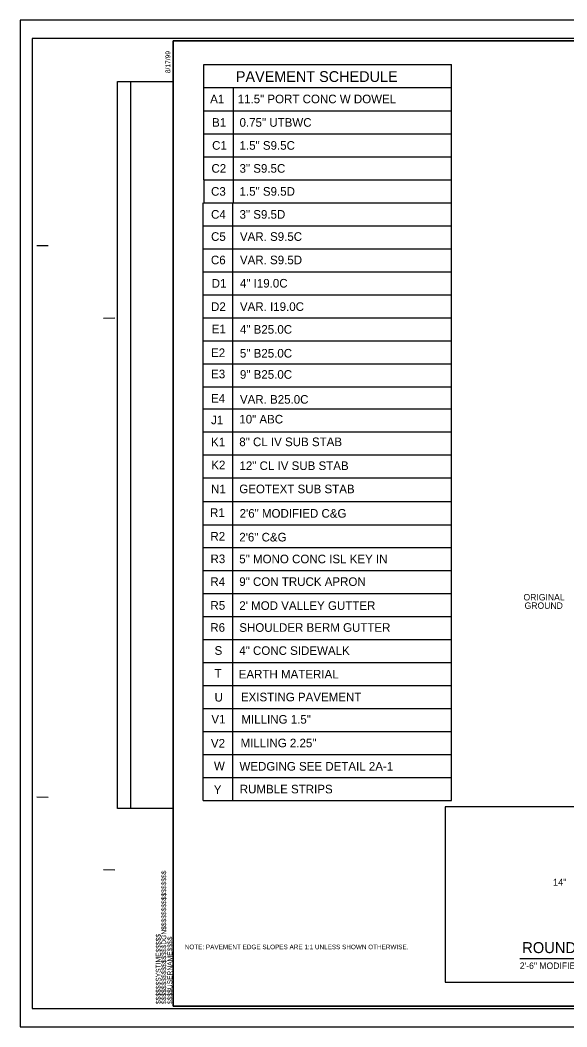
# Model space of a CAD drawing. Extents: x 1640342 to 1730599, y 538663 to 843747.
# Drawn here: x 1729840.7 to 1729959.6, y 538663.2 to 538882.2 of the extents above; entities that cross this region are included whole.
import ezdxf

# ---------------------------------------------------------------- set-up
doc = ezdxf.new("R2010")
doc.units = 0
for name, color, linetype in [('Default', 7, 'Continuous'), ('Old_Level_19', 7, 'Continuous'), ('Old_Level_21', 7, 'Continuous'), ('Sheet Block Revision CELL', 7, 'Continuous'), ('Sheet Plan CELL', 7, 'Continuous'), ('Sheet Plot Border Inside CELL', 7, 'Continuous'), ('Sheet Plot Border Outside CELL', 7, 'Continuous'), ('Typical Text Label CELL', 7, 'Continuous')]:
    doc.layers.add(name, color=color, linetype=linetype)

msp = doc.modelspace()

# ---------------------------------------------------------------- linework, layer by layer
at = {"layer": 'Old_Level_19'}
for p, q in [((1729880.62, 538872.54), (1729934.5, 538872.54)), ((1729880.62, 538867.54), (1729880.62, 538872.54)), ((1729934.5, 538712.47), (1729934.5, 538872.54)), ((1729880.62, 538862.46), (1729880.62, 538867.54)), ((1729880.62, 538867.54), (1729934.5, 538867.54)), ((1729887.11, 538862.46), (1729887.11, 538867.54)), ((1729880.62, 538857.46), (1729880.62, 538862.46)), ((1729880.62, 538862.46), (1729934.5, 538862.46)), ((1729887.11, 538857.46), (1729887.11, 538862.46)), ((1729880.62, 538857.46), (1729934.5, 538857.46)), ((1729880.62, 538852.46), (1729880.62, 538857.46)), ((1729887.11, 538852.46), (1729887.11, 538857.46)), ((1729880.62, 538852.46), (1729934.5, 538852.46)), ((1729880.62, 538847.46), (1729880.62, 538852.46)), ((1729887.11, 538847.46), (1729887.11, 538852.46)), ((1729880.62, 538847.46), (1729880.62, 538842.46)), ((1729880.62, 538847.46), (1729934.5, 538847.46)), ((1729887.11, 538842.46), (1729887.11, 538847.46)), ((1729880.48, 538712.47), (1729880.48, 538842.47)), ((1729880.62, 538842.46), (1729920.63, 538842.46)), ((1729880.62, 538842.46), (1729934.5, 538842.46)), ((1729886.98, 538712.47), (1729886.98, 538842.47)), ((1729880.62, 538837.46), (1729934.5, 538837.46)), ((1729880.62, 538832.46), (1729934.5, 538832.46)), ((1729880.62, 538827.46), (1729934.5, 538827.46)), ((1729880.62, 538822.46), (1729934.5, 538822.46)), ((1729880.62, 538817.46), (1729934.5, 538817.46)), ((1729880.62, 538812.46), (1729934.5, 538812.46)), ((1729880.62, 538807.46), (1729934.5, 538807.46)), ((1729880.62, 538802.46), (1729934.5, 538802.46)), ((1729880.48, 538797.67), (1729934.5, 538797.67)), ((1729880.48, 538792.67), (1729934.5, 538792.67)), ((1729880.48, 538787.67), (1729934.5, 538787.67)), ((1729880.48, 538782.67), (1729934.5, 538782.67)), ((1729880.48, 538777.47), (1729934.5, 538777.47)), ((1729880.48, 538772.46), (1729934.5, 538772.46)), ((1729880.48, 538767.47), (1729934.5, 538767.47)), ((1729880.48, 538762.47), (1729934.5, 538762.47)), ((1729880.48, 538757.47), (1729934.5, 538757.47)), ((1729880.48, 538752.47), (1729934.5, 538752.47)), ((1729880.48, 538747.47), (1729934.5, 538747.47)), ((1729880.48, 538742.47), (1729934.5, 538742.47)), ((1729880.48, 538737.47), (1729934.5, 538737.47)), ((1729880.48, 538732.47), (1729934.5, 538732.47)), ((1729880.48, 538727.47), (1729934.5, 538727.47)), ((1729880.48, 538722.47), (1729934.5, 538722.47)), ((1729880.48, 538717.47), (1729934.5, 538717.47)), ((1729880.48, 538712.47), (1729934.5, 538712.47))]:
    msp.add_line(p, q, dxfattribs=at)
at = {"layer": 'Sheet Block Revision CELL'}
msp.add_line((1729864.8, 538710.72), (1729864.79, 538868.85), dxfattribs=at)
msp.add_lwpolyline([(1729861.89, 538710.71), (1729861.89, 538868.84), (1729873.99, 538868.85), (1729873.99, 538710.72)], close=True, dxfattribs=at)
at = {"layer": 'Sheet Plan CELL'}
for p, q in [((1729873.99, 538877.72), (1729873.99, 538877.72)), ((1729844.29, 538833.21), (1729846.79, 538833.22)), ((1729858.82, 538817.41), (1729861.32, 538817.42)), ((1729844.3, 538713.22), (1729846.8, 538713.21)), ((1729858.82, 538697.42), (1729861.32, 538697.41)), ((1729873.99, 538667.72), (1729873.99, 538667.72))]:
    msp.add_line(p, q, dxfattribs=at)
for points in [[(1730174, 538877.72), (1729873.99, 538877.72), (1729873.99, 538667.72), (1730173.99, 538667.72)], [(1729873.99, 538667.72), (1729873.99, 538877.71), (1730133.98, 538877.72), (1730133.99, 538847.71), (1730173.99, 538847.71), (1730173.99, 538667.72)]]:
    msp.add_lwpolyline(points, close=True, dxfattribs=at)
at = {"layer": 'Sheet Plot Border Inside CELL'}
msp.add_lwpolyline([(1729843.29, 538667.22), (1730176.49, 538667.22), (1730176.49, 538878.22), (1729843.29, 538878.22)], close=True, dxfattribs=at)
at = {"layer": 'Sheet Plot Border Outside CELL'}
msp.add_lwpolyline([(1729840.69, 538663.22), (1730177.39, 538663.22), (1730177.39, 538882.22), (1729840.69, 538882.22)], close=True, dxfattribs=at)
at = {"layer": 'Typical Text Label CELL'}
msp.add_line((1729949.37, 538678.08), (1729986.68, 538678.08), dxfattribs=at)
msp.add_lwpolyline([(1729933.1, 538672.93), (1730006.83, 538672.93), (1730006.83, 538711.05), (1729933.1, 538711.05)], close=True, dxfattribs=at)

# ---------------------------------------------------------------- texts
at = {"layer": 'Default'}
for s, height, p in [('ORIGINAL', 1.4, (1729950.16, 538755.98)), ('GROUND', 1.4, (1729950.4, 538754.15)), ('14"', 1.5, (1729956.56, 538693.92)), ('NOTE: PAVEMENT EDGE SLOPES ARE 1:1 UNLESS SHOWN OTHERWISE.', 1, (1729876.49, 538680.1))]:
    msp.add_text(s, height=height, dxfattribs=at).set_placement(p)
at = {"layer": 'Old_Level_21'}
for s, height, p in [('PAVEMENT SCHEDULE', 2.3438, (1729887.6, 538868.77)), ('A1', 1.875, (1729882.02, 538864.13)), ('11.5" PORT CONC W DOWEL', 1.875, (1729888, 538864.13)), ('B1', 1.875, (1729882.44, 538859.02)), ('0.75" UTBWC', 1.875, (1729888.41, 538859.02)), ('C1', 1.875, (1729882.44, 538854.02)), ('1.5" S9.5C', 1.875, (1729888.41, 538854.02)), ('C2', 1.875, (1729882.3, 538849.02)), ('3" S9.5C', 1.875, (1729888.41, 538849.02)), ('C3', 1.875, (1729882.21, 538844.02)), ('1.5" S9.5D', 1.875, (1729888.41, 538844.02)), ('C4', 1.875, (1729882.21, 538839.02)), ('3" S9.5D', 1.875, (1729888.41, 538839.02)), ('C5', 1.875, (1729882.21, 538834.2)), ('VAR. S9.5C', 1.875, (1729888.49, 538834.2)), ('C6', 1.875, (1729882.19, 538829.1)), ('VAR. S9.5D', 1.875, (1729888.49, 538829.11)), ('D1', 1.875, (1729882.35, 538824.02)), ('4" I19.0C', 1.875, (1729888.49, 538824.04)), ('D2', 1.875, (1729882.21, 538818.95)), ('VAR. I19.0C', 1.875, (1729888.49, 538818.96)), ('E1', 1.875, (1729882.35, 538814.1)), ('4" B25.0C', 1.875, (1729888.49, 538814)), ('E2', 1.875, (1729882.21, 538808.91)), ('5" B25.0C', 1.875, (1729888.49, 538808.81)), ('E3', 1.875, (1729882.22, 538804.3)), ('9" B25.0C', 1.875, (1729888.49, 538804.2)), ('E4', 1.875, (1729882.2, 538799)), ('VAR. B25.0C', 1.875, (1729888.49, 538798.78)), ('J1', 1.875, (1729882.21, 538794.3)), ('10" ABC', 1.875, (1729888.35, 538794.47)), ('K1', 1.875, (1729882.21, 538789.5)), ('8" CL IV SUB STAB', 1.875, (1729888.35, 538789.54)), ('K2', 1.875, (1729882.25, 538784.51)), ('12" CL IV SUB STAB', 1.875, (1729888.39, 538784.35)), ('N1', 1.875, (1729882.21, 538779.28)), ('GEOTEXT SUB STAB', 1.875, (1729888.35, 538779.3)), ('R1', 1.875, (1729881.99, 538774.14)), ('2\'6" MODIFIED C&G', 1.875, (1729888.42, 538773.98)), ('R2', 1.875, (1729882.07, 538769)), ('2\'6" C&G', 1.875, (1729888.35, 538768.81)), ('R3', 1.875, (1729882.09, 538764.09)), ('5" MONO CONC ISL KEY IN', 1.875, (1729888.35, 538764.06)), ('R4', 1.875, (1729882.07, 538759.13)), ('9" CON TRUCK APRON', 1.875, (1729888.35, 538759.13)), ('R5', 1.875, (1729882.08, 538753.96)), ("2' MOD VALLEY GUTTER", 1.875, (1729888.35, 538753.92)), ('R6', 1.875, (1729882.05, 538749.16)), ('SHOULDER BERM GUTTER', 1.875, (1729888.35, 538749.15)), ('S', 1.88, (1729882.97, 538744.15)), ('4" CONC SIDEWALK', 1.875, (1729888.35, 538744.13)), ('T', 1.88, (1729882.97, 538739.16)), ('EARTH MATERIAL', 1.875, (1729888.23, 538739)), ('U', 1.88, (1729882.97, 538733.98)), ('EXISTING PAVEMENT', 1.875, (1729888.7, 538734.03)), ('V1', 1.875, (1729882.28, 538729.21)), ('MILLING 1.5"', 1.875, (1729888.81, 538729.17)), ('V2', 1.875, (1729882.18, 538723.97)), ('MILLING 2.25"', 1.875, (1729888.63, 538724.03)), ('W', 1.88, (1729882.84, 538719.03)), ('WEDGING SEE DETAIL 2A-1', 1.875, (1729888.39, 538718.96)), ('Y', 1.88, (1729882.8, 538713.9)), ('RUMBLE STRIPS', 1.875, (1729888.46, 538714.01))]:
    msp.add_text(s, height=height, dxfattribs=at).set_placement(p)
at = {"layer": 'Sheet Plan CELL'}
for s, p in [('8/17/99', (1729873.35, 538870.67)), ('$$$$$$$$$$$$$$$$DGN$$$$$$$$$$$$$$$$', (1729872.46, 538668.19)), ('$$$$$$SYSTIME$$$$$', (1729871.25, 538668.19)), ('$$$$USERNAME$$$$', (1729873.77, 538668.19))]:
    msp.add_text(s, height=1.05, rotation=90, dxfattribs=at).set_placement(p)
at = {"layer": 'Typical Text Label CELL'}
for s, height, p in [('ROUNDABOUT DETAIL 1', 2.3871, (1729949.88, 538679.26)), ('2\'-6" MODIFIED CURB & GUTTER DETAIL', 1.4, (1729949.36, 538675.82))]:
    msp.add_text(s, height=height, dxfattribs=at).set_placement(p)

doc.saveas('drawing.dxf')
